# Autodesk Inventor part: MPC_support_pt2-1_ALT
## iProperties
Shininess: 64.0
Length Units: 11269
Angle Units: 11279
Time Units: 11290
Mass Units: 11283
Length Display Precision: 3
Angle Display Precision: 2
Compacted: True
Part Number: MPC_support_pt2-1_ALT
Document SubType Name: Modeling
Created: 2004-08
Designer: John Blackburn
Manufacturer: Standard
Standards Organization: Custom
Material: Aluminum-6061
Density: 0.0
Volumn: 0.0
Area: 0.0
PropertySet Name: Model Information
Control State: 0
Master: False
Checked Out: False
Author: John Blackburn
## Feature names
1. Extrusion1
2. Hole1
3. Hole2
